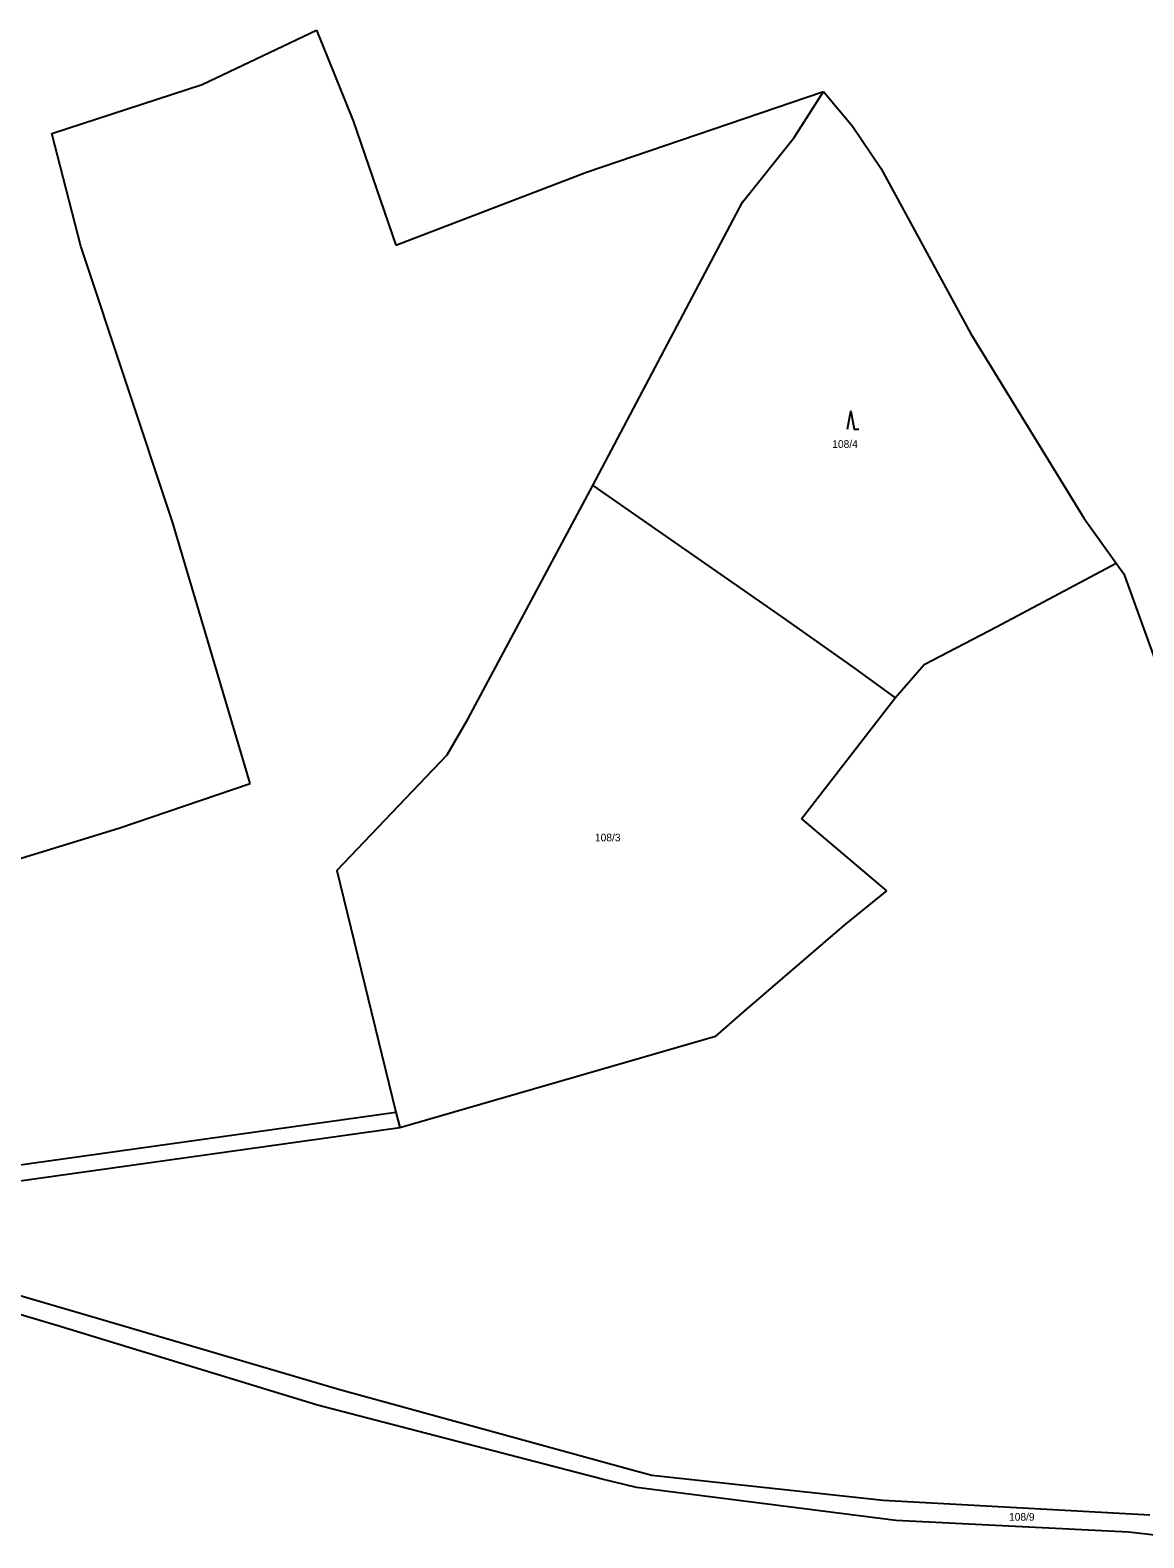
# Model space of a CAD drawing. Extents: x -780000 to -777378, y -1011169 to -1009297.
# Drawn here: x -778429.6 to -778181.9, y -1010109.8 to -1009774.5 of the extents above; entities that cross this region are included whole.
import ezdxf

# ---------------------------------------------------------------- set-up
doc = ezdxf.new("R2010")
doc.units = 0
for name, color, linetype in [('Default', 7, 'Continuous'), ('KN_HRANICE', 7, 'Continuous'), ('KN_KULTURY', 7, 'Continuous'), ('KN_PARCELY', 7, 'Continuous')]:
    doc.layers.add(name, color=color, linetype=linetype)

# ---------------------------------------------------------------- blocks, each defined once
blk = doc.blocks.new('308')
at = {"layer": 'Default'}
blk.add_lwpolyline([(-0.75, 0), (0, 4), (0.75, 0), (1.75, 0)], dxfattribs=at)

msp = doc.modelspace()

# ---------------------------------------------------------------- linework, layer by layer
at = {"layer": 'KN_HRANICE'}
for p, q in [((-778391.39, -1009786.56), (-778365.92, -1009774.47)), ((-778365.92, -1009774.47), (-778357.79, -1009794.65)), ((-778424.79, -1009797.42), (-778391.39, -1009786.56)), ((-778305.88, -1009806.04), (-778253.23, -1009788.09)), ((-778259.7, -1009798.31), (-778253.23, -1009788.09)), ((-778253.23, -1009788.09), (-778246.76, -1009795.86)), ((-778357.79, -1009794.65), (-778348.3, -1009822.26)), ((-778246.76, -1009795.86), (-778240.42, -1009805.17)), ((-778418.38, -1009822.49), (-778424.79, -1009797.42)), ((-778271.19, -1009812.73), (-778259.7, -1009798.31)), ((-778348.3, -1009822.26), (-778305.88, -1009806.04)), ((-778240.42, -1009805.17), (-778220.4, -1009842.01)), ((-778304.51, -1009875.73), (-778271.19, -1009812.73)), ((-778397.98, -1009883.84), (-778418.38, -1009822.49)), ((-778220.4, -1009842.01), (-778195.2, -1009883.12)), ((-778332.32, -1009927.75), (-778304.51, -1009875.73)), ((-778304.51, -1009875.73), (-778262.42, -1009905)), ((-778195.2, -1009883.12), (-778188.09, -1009893.03)), ((-778390.73, -1009908.28), (-778397.98, -1009883.84)), ((-778214.71, -1009907.2), (-778188.09, -1009893.03)), ((-778188.09, -1009893.03), (-778186.4, -1009895.39)), ((-778186.4, -1009895.39), (-778186.19, -1009895.98)), ((-778186.19, -1009895.98), (-778176.01, -1009924.09)), ((-778262.42, -1009905), (-778246.53, -1009916.19)), ((-778380.68, -1009942.03), (-778390.73, -1009908.28)), ((-778230.81, -1009915.54), (-778214.71, -1009907.2)), ((-778246.53, -1009916.19), (-778237.26, -1009922.95)), ((-778237.26, -1009922.95), (-778230.81, -1009915.54)), ((-778258.11, -1009949.88), (-778237.26, -1009922.95)), ((-778336.92, -1009935.65), (-778332.32, -1009927.75)), ((-778361.41, -1009961.37), (-778336.92, -1009935.65)), ((-778409.93, -1009951.93), (-778380.68, -1009942.03)), ((-778258.11, -1009949.88), (-778239.17, -1009965.87)), ((-778441.85, -1009961.74), (-778409.93, -1009951.93)), ((-778361.41, -1009961.37), (-778348.28, -1010015.11)), ((-778239.17, -1009965.87), (-778248.57, -1009973.51)), ((-778248.57, -1009973.51), (-778271.29, -1009993.02)), ((-778271.29, -1009993.02), (-778277.25, -1009998.22)), ((-778294.15, -1010003.11), (-778277.25, -1009998.22)), ((-778347.45, -1010018.54), (-778294.15, -1010003.11)), ((-778497.51, -1010036.07), (-778348.28, -1010015.11)), ((-778348.28, -1010015.11), (-778347.45, -1010018.54)), ((-778465.13, -1010035.06), (-778347.45, -1010018.54)), ((-778423.7, -1010062.57), (-778466.13, -1010049.97)), ((-778448.54, -1010051.05), (-778413.41, -1010061.34)), ((-778365.7, -1010080.27), (-778423.7, -1010062.57)), ((-778413.41, -1010061.34), (-778360.73, -1010076.84)), ((-778360.73, -1010076.84), (-778296.58, -1010094.47)), ((-778302.43, -1010096.77), (-778365.7, -1010080.27)), ((-778294.76, -1010098.57), (-778302.43, -1010096.77)), ((-778296.58, -1010094.47), (-778291.4, -1010095.84)), ((-778291.4, -1010095.84), (-778239.95, -1010101.4)), ((-778237.09, -1010105.96), (-778294.76, -1010098.57)), ((-778239.95, -1010101.4), (-778180.65, -1010104.69)), ((-778185.39, -1010108.53), (-778237.09, -1010105.96)), ((-778174.14, -1010109.8), (-778185.39, -1010108.53))]:
    msp.add_line(p, q, dxfattribs=at)

# ---------------------------------------------------------------- block references
at = {"layer": 'KN_KULTURY'}
msp.add_blockref('308', (-778247.11, -1009863.2), dxfattribs=at)

# ---------------------------------------------------------------- texts
at = {"layer": 'KN_PARCELY'}
for s, p in [('108/4', (-778251.25, -1009867.37)), ('108/3', (-778304.03, -1009954.89)), ('108/9', (-778211.93, -1010105.98))]:
    msp.add_text(s, height=1.7, dxfattribs=at).set_placement(p)

doc.saveas('drawing.dxf')
